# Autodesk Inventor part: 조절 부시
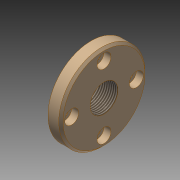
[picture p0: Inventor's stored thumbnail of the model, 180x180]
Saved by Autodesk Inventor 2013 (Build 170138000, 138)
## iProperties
Created: 2023-11
Part Number: 조절 부시
Material: 강철, 연강
Document SubType Name: Modeling
Designer: mdu-01
Density: 1 g/cm^3
Author: mdu-01
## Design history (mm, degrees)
sketch "스케치1"
  geometry: L1 (-7, 0)-(6, 0); L2 (6, 0)-(6, 19); L3 (5, 20)-(0, 20); L4 (0, 20)-(0, 9); L5 (0, 9)-(-6, 9); L6 (-7, 8)-(-7, 0); L7 (6, 19)-(5, 20); L8 (-6, 9)-(-7, 8); 3 further points
  constraints: 18 end point, 6 point on line, 1 horizontal, 1 parallel, 1 vertical
  dimensions: "d0" = 6 distance between parallel lines of L2 L4; "d2" = 18 diameter of L5 L1; "d3" = 40 diameter of L3 L1; "d4" = 7 distance between parallel lines of L6 L4; "d5" = 1 distance of L2.end point (6, 20); "d6" = 1 distance of L3.start point (6, 20) (= d5); "d7" = 1 distance of L5.end point (-7, 9); "d8" = 1 distance of L6.start point (-7, 9) (= d7)
revolve "회전1" sketch "스케치1" stored, may be unused: angle "d9" = 90 deg
hole "구멍1" diameter "d12" = 12.917; stored, may be unused: countersink angle "d16" = 90 deg, drill point angle "d18" = 118 deg; dims "d10" = 10, "d11" = 10, "d13" = 6, "d14" = 4, "d15" = 2, "d17" = 8
sketch "스케치2"
  geometry: C1 r 1.23 at (0, 15) reference; 1 further point
hole "구멍2" sketch "스케치2" at (0, 15) diameter "d19" = 3.4; stored, may be unused: countersink angle "d23" = 90 deg, drill point angle "d25" = 118 deg; dims "d20" = 6, "d21" = 6.5, "d22" = 3.3, "d24" = 8
node "솔리드1"
pattern_circular "원형 패턴1" dims angle "d27" = 360 deg
node "참조1"
